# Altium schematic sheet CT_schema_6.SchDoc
size 297 x 173 mm
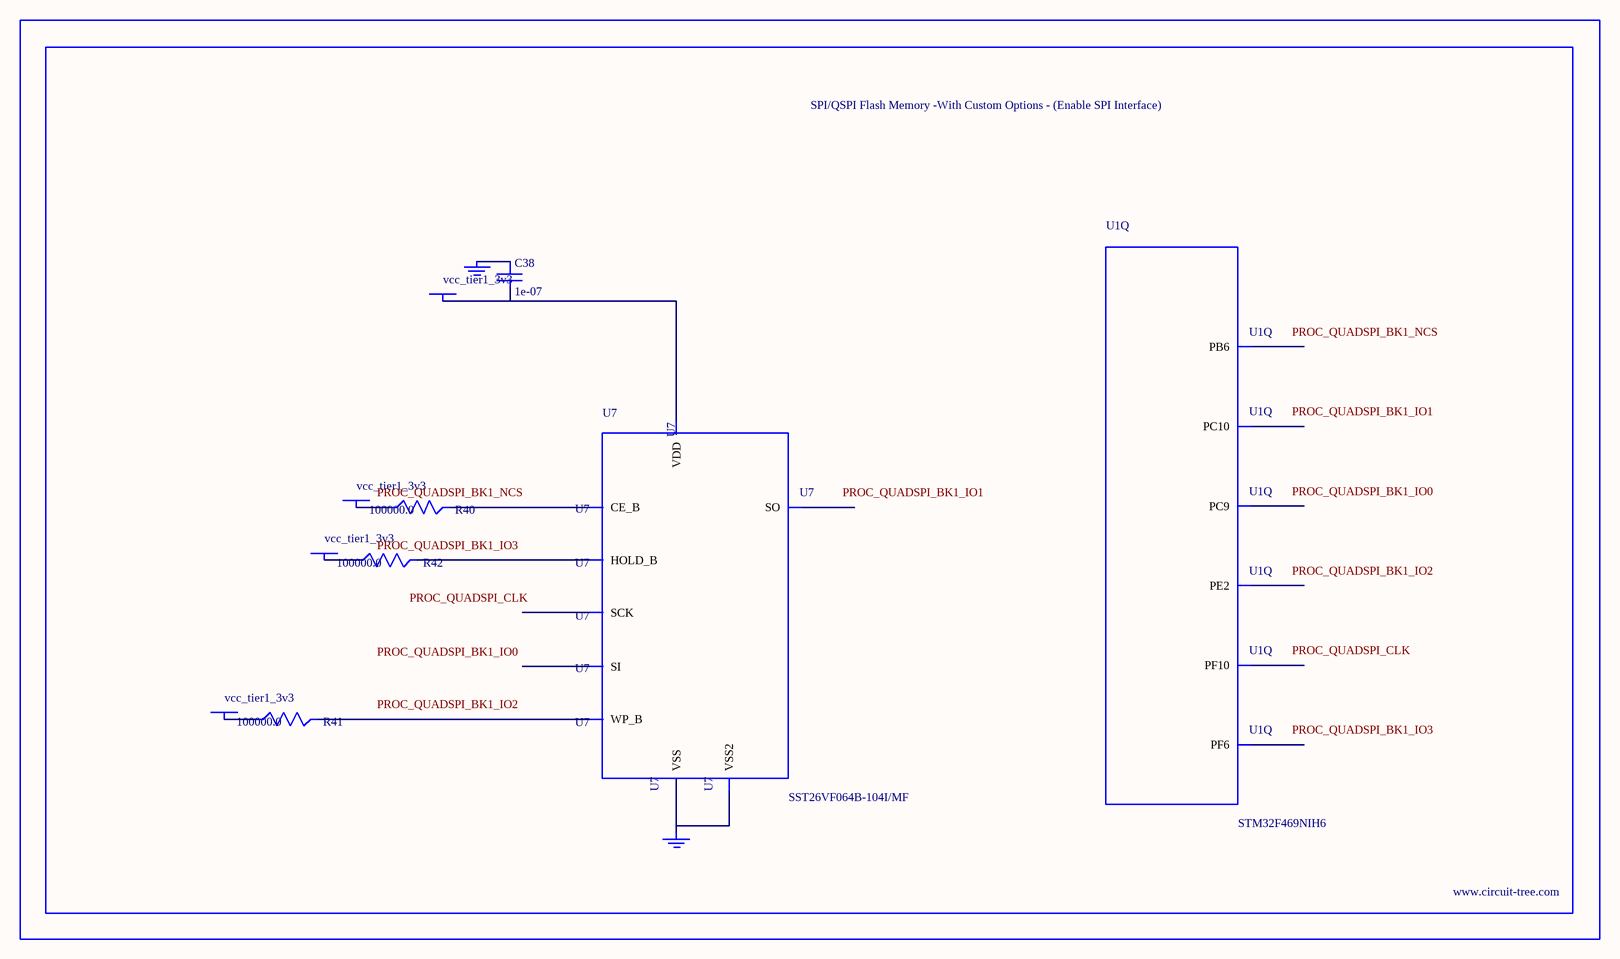
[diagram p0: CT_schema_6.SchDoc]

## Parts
BORDER5  (no value)
C38  1e-07  [C0402]
GND_INSTANCE_5_0  (no value)
GND_INSTANCE_5_1  (no value)
POWER_INSTANCE_5_0  vcc_tier1_3v3
POWER_INSTANCE_5_1  vcc_tier1_3v3
POWER_INSTANCE_5_2  vcc_tier1_3v3
POWER_INSTANCE_5_3  vcc_tier1_3v3
R40  100000.0  [R0603]
R41  100000.0  [R0603]
R42  100000.0  [R0603]
U1  STM32F469NIH6  [TFBGA216]  (part Q of 17)
U7  SST26VF064B-104I/MF  [WFDN-8]

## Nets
NetC38_1: C38.1 GND_INSTANCE_5_0.0(GND)
NetC38_2: C38.2 POWER_INSTANCE_5_3.0(PWR) U7.8(VDD)
NetGND_INSTANCE_5_1_0: GND_INSTANCE_5_1.0(GND) U7.4(VSS) U7.9(VSS2)
NetPOWER_INSTANCE_5_0_0: POWER_INSTANCE_5_0.0(PWR) R40.1
NetPOWER_INSTANCE_5_1_0: POWER_INSTANCE_5_1.0(PWR) R41.1
NetPOWER_INSTANCE_5_2_0: POWER_INSTANCE_5_2.0(PWR) R42.1
NetR40_2: R40.2 U7.1(CE_B)
NetR41_2: R41.2 U7.3(WP_B)
NetR42_2: R42.2 U7.7(HOLD_B)

Not connected (* = marked no-connect by the designer): U1 A3(PE2) B6(PB6) B14(PC10) F14(PC9) K2(PF6) L1(PF10); U7 2(SO) 5(SI) 6(SCK)

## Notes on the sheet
- Labels drawn without touching a wire or pin: PROC_QUADSPI_BK1_IO0, PROC_QUADSPI_BK1_IO1, PROC_QUADSPI_BK1_IO2, PROC_QUADSPI_BK1_IO3, PROC_QUADSPI_BK1_NCS, PROC_QUADSPI_CLK

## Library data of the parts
BORDER5 = BORDER_PAGE5
C38 = C0402C104K3RACTU
GND_INSTANCE_5_0 GND_INSTANCE_5_1 = GND
POWER_INSTANCE_5_0-POWER_INSTANCE_5_3 = PWR
R40-R42 = RC0603JR-07100KL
